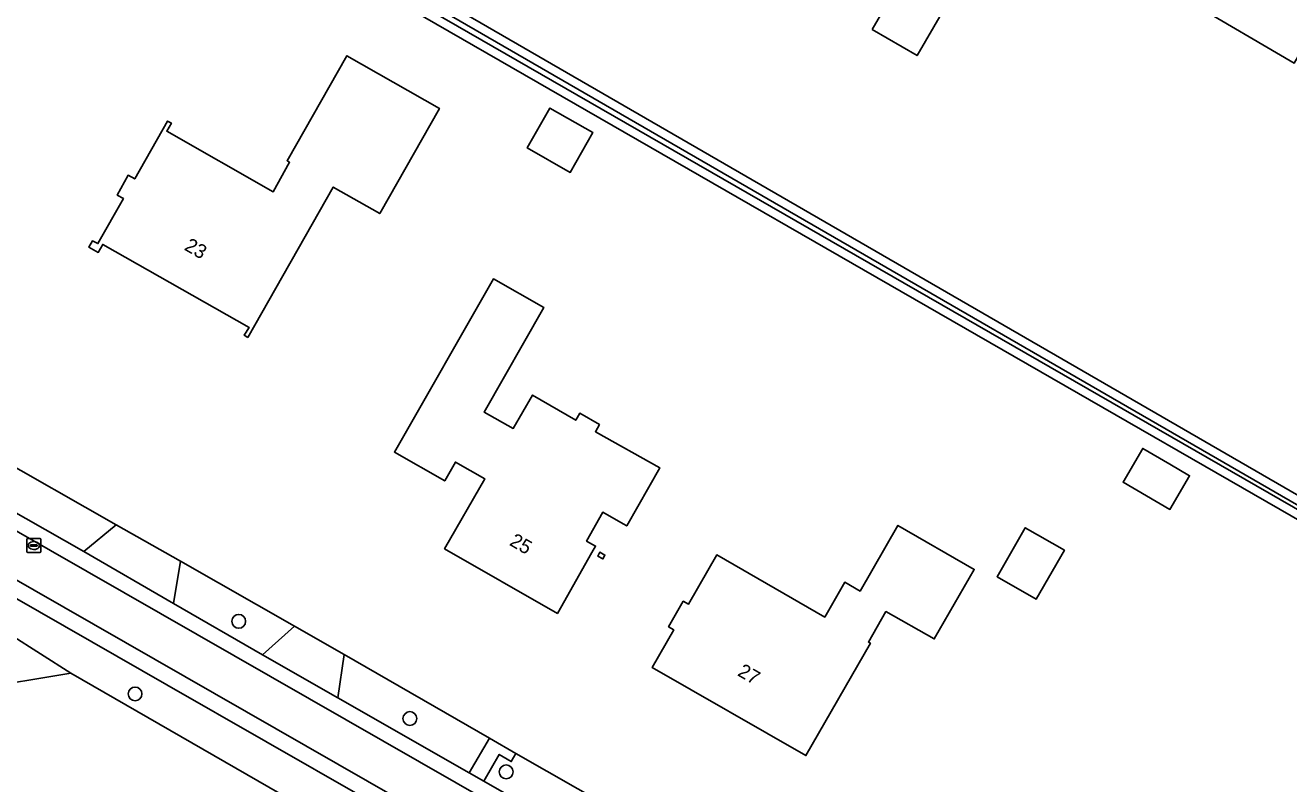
# Model space of a CAD drawing. Extents: x 156502 to 159075, y 384229 to 386100.
# Drawn here: x 157051.2 to 157141.1, y 385765 to 385818.9 of the extents above; entities that cross this region are included whole.
import ezdxf

# ---------------------------------------------------------------- set-up
doc = ezdxf.new("R2010")
doc.units = 0
for name, color, linetype in [('IMGEO_Berm_groen', 7, 'Continuous'), ('IMGEO_Boom', 7, 'Continuous'), ('IMGEO_Erf', 7, 'Continuous'), ('IMGEO_Groenvoorziening', 7, 'Continuous'), ('IMGEO_Hek', 7, 'Continuous'), ('IMGEO_Muur', 7, 'Continuous'), ('IMGEO_Oever', 7, 'Continuous'), ('IMGEO_Pand', 7, 'Continuous'), ('IMGEO_Pand_nummerreeks', 7, 'Continuous'), ('IMGEO_Rijbaan_lokaal_gesloten', 7, 'Continuous'), ('IMGEO_Rijbaan_lokaal_halfverhard', 7, 'Continuous'), ('IMGEO_Rijbaan_lokaal_open', 7, 'Continuous'), ('IMGEO_Rioolput', 7, 'Continuous'), ('IMGEO_Voetpad_open', 7, 'Continuous'), ('IMGEO_Waterloop', 7, 'Continuous')]:
    doc.layers.add(name, color=color, linetype=linetype)

msp = doc.modelspace()

# ---------------------------------------------------------------- linework, layer by layer
at = {"layer": 'IMGEO_Berm_groen'}
for points in [[(157062.278, 385780.824), (157061.801, 385777.83), (157068.127, 385774.18), (157070.393, 385776.216)], [(157073.942, 385774.201), (157073.474, 385771.108), (157082.83, 385765.787), (157084.266, 385768.252)], [(157086.152, 385767.162), (157085.817, 385766.586), (157084.961, 385767.091), (157083.861, 385765.187), (157098.368, 385756.889), (157101.744, 385758.276)]]:
    msp.add_lwpolyline(points, close=True, dxfattribs=at)
at = {"layer": 'IMGEO_Boom'}
for centre in [(157066.435, 385776.556), (157059.057, 385771.395), (157078.606, 385769.643), (157085.455, 385765.849)]:
    msp.add_circle(centre, 0.489, dxfattribs=at)
at = {"layer": 'IMGEO_Erf'}
for points in [[(157042.786, 385843.67), (157065.314, 385829.887), (157068.346, 385827.983), (157173.435, 385767.228), (157172.677, 385766.006), (157064.372, 385828.327), (157041.356, 385841.775)], [(157146.528, 385824.906), (157141.519, 385816.264), (157134.144, 385820.573)], [(157048.701, 385788.533), (157057.714, 385783.415), (157062.278, 385780.824), (157070.393, 385776.216), (157073.942, 385774.201), (157084.266, 385768.252), (157086.152, 385767.162), (157101.744, 385758.276), (157104.7, 385756.591), (157109.515, 385753.847), (157111.678, 385752.607), (157114.022, 385751.264), (157119.086, 385748.362), (157121.522, 385746.887), (157123.015, 385746.039), (157125.376, 385744.699), (157127.595, 385743.439), (157130.921, 385741.579), (157131.197, 385741.421), (157144.11, 385733.995)], [(157147.432, 385715.812), (157133.773, 385723.654), (157134.821, 385725.475), (157132.597, 385726.756), (157131.792, 385725.315), (157113.077, 385736.144), (157108.687, 385738.705), (157108.063, 385741.81), (157080.131, 385758.103), (157080.304, 385758.402), (157074.239, 385761.861), (157074.046, 385761.597), (157054.491, 385772.88), (157047.62, 385771.736)]]:
    msp.add_lwpolyline(points, dxfattribs=at)
for points in [[(157111.485, 385818.64), (157113.86, 385822.753), (157117.067, 385820.902), (157114.692, 385816.789)], [(157067.08, 385796.742), (157066.82, 385796.909), (157067.171, 385797.456), (157056.763, 385803.368), (157056.438, 385802.793), (157055.779, 385803.165), (157056.02, 385803.617), (157056.419, 385803.418), (157058.233, 385806.623), (157057.796, 385806.877), (157058.566, 385808.281), (157059.03, 385808.027), (157061.37, 385812.141), (157061.645, 385811.981), (157061.316, 385811.411), (157068.883, 385807.115), (157070.049, 385809.211), (157069.866, 385809.315), (157074.122, 385816.781), (157080.705, 385813.039), (157076.458, 385805.561), (157073.154, 385807.438)], [(157090.018, 385808.489), (157086.958, 385810.227), (157088.567, 385813.06), (157091.627, 385811.322)], [(157094.034, 385783.344), (157093.774, 385783.484), (157092.329, 385784.314), (157091.181, 385782.261), (157091.819, 385781.904), (157091.56, 385781.44), (157089.098, 385777.114), (157081.073, 385781.715), (157083.929, 385786.699), (157081.847, 385787.885), (157081.084, 385786.547), (157077.502, 385788.588), (157084.548, 385800.906), (157088.147, 385798.874), (157083.885, 385791.439), (157085.956, 385790.275), (157087.339, 385792.644), (157090.403, 385790.86), (157090.692, 385791.357), (157092.087, 385790.545), (157091.801, 385790.041), (157096.381, 385787.475)], [(157132.674, 385787.725), (157134.071, 385786.91), (157132.672, 385784.511), (157129.345, 385786.451), (157130.745, 385788.851)], [(157113.324, 385783.376), (157118.757, 385780.244), (157115.909, 385775.303), (157112.473, 385777.255), (157111.225, 385775.078), (157111.364, 385774.999), (157106.783, 385767.009), (157095.843, 385773.267), (157097.372, 385775.944), (157097.005, 385776.166), (157098.051, 385777.989), (157098.424, 385777.775), (157100.433, 385781.277), (157108.121, 385776.862), (157109.544, 385779.339), (157110.637, 385778.713)], [(157122.386, 385783.214), (157125.162, 385781.614), (157123.152, 385778.127), (157120.376, 385779.727)], [(157092.485, 385781.264), (157092.341, 385780.999), (157091.968, 385781.202), (157092.112, 385781.467)]]:
    msp.add_lwpolyline(points, close=True, dxfattribs=at)
at = {"layer": 'IMGEO_Groenvoorziening'}
for points in [[(157048.701, 385788.533), (157048.579, 385793.832), (157048.565, 385801.621), (157048.314, 385802.061), (157045.399, 385797.293), (157048.506, 385785.444), (157055.407, 385781.512), (157057.714, 385783.415)], [(157048.686, 385779.263), (157047.987, 385776.991), (157054.491, 385772.88), (157074.046, 385761.597), (157074.239, 385761.861), (157075.399, 385763.984), (157061.322, 385772.036)], [(157047.987, 385776.991), (157047.892, 385775.032), (157046.412, 385772.497), (157046.044, 385771.329), (157045.742, 385769.133), (157042.959, 385732.042), (157041.74, 385723.537), (157053.67, 385716.85), (157053.851, 385718.152), (157042.415, 385724.776), (157044.054, 385732.143), (157045.294, 385741.29), (157045.604, 385750.127), (157045.953, 385758.926), (157047.62, 385771.736), (157054.491, 385772.88)]]:
    msp.add_lwpolyline(points, close=True, dxfattribs=at)
at = {"layer": 'IMGEO_Hek'}
for points in [[(157048.314, 385802.061), (157048.565, 385801.621), (157048.579, 385793.832), (157048.701, 385788.533), (157057.714, 385783.415)], [(157057.714, 385783.415), (157062.278, 385780.824)], [(157062.278, 385780.824), (157070.393, 385776.216)], [(157070.393, 385776.216), (157073.942, 385774.201)], [(157073.942, 385774.201), (157084.266, 385768.252)], [(157074.046, 385761.597), (157054.491, 385772.88)], [(157084.266, 385768.252), (157086.152, 385767.162)], [(157086.152, 385767.162), (157101.744, 385758.276)]]:
    msp.add_lwpolyline(points, dxfattribs=at)
at = {"layer": 'IMGEO_Muur'}
for points in [[(157091.968, 385781.202), (157092.112, 385781.467), (157092.485, 385781.264)], [(157092.341, 385780.999), (157091.968, 385781.202)], [(157092.485, 385781.264), (157092.341, 385780.999)]]:
    msp.add_lwpolyline(points, dxfattribs=at)
at = {"layer": 'IMGEO_Oever'}
for points in [[(157036.041, 385834.964), (157036.588, 385835.458), (157041.356, 385841.775), (157064.372, 385828.327), (157172.677, 385766.006), (157173.435, 385767.228), (157068.346, 385827.983), (157065.314, 385829.887), (157042.786, 385843.67), (157047.224, 385849.55), (157062.244, 385869.451), (157069.688, 385879.771), (157078.432, 385891.893), (157077.479, 385892.687), (157076.448, 385893.546)], [(157042.409, 385843.171), (157064.986, 385829.358), (157068.025, 385827.45), (157172.568, 385767.011), (157172.466, 385766.846), (157064.684, 385828.865), (157041.733, 385842.275)]]:
    msp.add_lwpolyline(points, dxfattribs=at)
at = {"layer": 'IMGEO_Pand'}
for points in [[(157134.715, 385841.68), (157130.951, 385835.263), (157140.002, 385829.967), (157139.464, 385829.042), (157139.17, 385829.213), (157134.144, 385820.573), (157141.519, 385816.264), (157146.528, 385824.906), (157141.44, 385827.871), (157141.989, 385828.812), (157142.29, 385828.637), (157146.045, 385835.121)], [(157111.485, 385818.64), (157114.692, 385816.789), (157117.067, 385820.902), (157113.86, 385822.753)], [(157067.08, 385796.742), (157073.154, 385807.438), (157076.458, 385805.561), (157080.705, 385813.039), (157074.122, 385816.781), (157069.866, 385809.315), (157070.049, 385809.211), (157068.883, 385807.115), (157061.316, 385811.411), (157061.645, 385811.981), (157061.37, 385812.141), (157059.03, 385808.027), (157058.566, 385808.281), (157057.796, 385806.877), (157058.233, 385806.623), (157056.419, 385803.418), (157056.02, 385803.617), (157055.779, 385803.165), (157056.438, 385802.793), (157056.763, 385803.368), (157067.171, 385797.456), (157066.82, 385796.909)], [(157086.958, 385810.227), (157090.018, 385808.489), (157091.627, 385811.322), (157088.567, 385813.06)], [(157093.774, 385783.484), (157094.034, 385783.344), (157096.381, 385787.475), (157091.801, 385790.041), (157092.087, 385790.545), (157090.692, 385791.357), (157090.403, 385790.86), (157087.339, 385792.644), (157085.956, 385790.275), (157083.885, 385791.439), (157088.147, 385798.874), (157084.548, 385800.906), (157077.502, 385788.588), (157081.084, 385786.547), (157081.847, 385787.885), (157083.929, 385786.699), (157081.073, 385781.715), (157089.098, 385777.114), (157091.56, 385781.44), (157091.819, 385781.904), (157091.181, 385782.261), (157092.329, 385784.314)], [(157129.345, 385786.451), (157132.672, 385784.511), (157134.071, 385786.91), (157132.674, 385787.725), (157130.745, 385788.851)], [(157106.783, 385767.009), (157111.364, 385774.999), (157111.225, 385775.078), (157112.473, 385777.255), (157115.909, 385775.303), (157118.757, 385780.244), (157113.324, 385783.376), (157110.637, 385778.713), (157109.544, 385779.339), (157108.121, 385776.862), (157100.433, 385781.277), (157098.424, 385777.775), (157098.051, 385777.989), (157097.005, 385776.166), (157097.372, 385775.944), (157095.843, 385773.267)], [(157120.376, 385779.727), (157123.152, 385778.127), (157125.162, 385781.614), (157122.386, 385783.214)], [(157092.112, 385781.467), (157091.968, 385781.202), (157092.341, 385780.999), (157092.485, 385781.264)]]:
    msp.add_lwpolyline(points, close=True, dxfattribs=at)
at = {"layer": 'IMGEO_Rijbaan_lokaal_gesloten'}
for points in [[(157155.604, 385722.866), (157042.417, 385787.656)], [(157047.474, 385781.289), (157153.385, 385720.619)]]:
    msp.add_lwpolyline(points, dxfattribs=at)
at = {"layer": 'IMGEO_Rijbaan_lokaal_halfverhard'}
for points in [[(157042.417, 385787.656), (157155.604, 385722.866)], [(157156.009, 385723.887), (157148.433, 385728.196), (157142.675, 385731.515), (157129.529, 385739.04), (157126.176, 385740.973), (157123.969, 385742.234), (157121.61, 385743.581), (157120.125, 385744.429), (157117.587, 385745.884), (157112.582, 385748.755), (157110.239, 385750.099), (157105.201, 385752.99), (157098.368, 385756.889), (157083.861, 385765.187), (157082.83, 385765.787), (157073.474, 385771.108), (157068.127, 385774.18), (157061.801, 385777.83), (157055.407, 385781.512), (157048.506, 385785.444), (157044.158, 385787.921)], [(157047.474, 385781.289), (157047.846, 385779.743), (157048.686, 385779.263), (157061.322, 385772.036), (157075.399, 385763.984), (157081.499, 385760.496), (157110.277, 385744.036), (157115.815, 385740.863), (157122.692, 385736.917), (157122.862, 385737.211), (157131.139, 385732.504), (157143.135, 385725.639), (157151.556, 385720.809)], [(157153.385, 385720.619), (157047.474, 385781.289)]]:
    msp.add_lwpolyline(points, dxfattribs=at)
at = {"layer": 'IMGEO_Rijbaan_lokaal_open'}
for points in [[(157055.407, 385781.512), (157061.801, 385777.83), (157062.278, 385780.824), (157057.714, 385783.415)], [(157068.127, 385774.18), (157073.474, 385771.108), (157073.942, 385774.201), (157070.393, 385776.216)]]:
    msp.add_lwpolyline(points, close=True, dxfattribs=at)
at = {"layer": 'IMGEO_Rioolput'}
for p, q in [((157051.354, 385781.521), (157051.354, 385782.373)), ((157051.429, 385782.447), (157052.281, 385782.447)), ((157051.613, 385781.941), (157051.613, 385781.953)), ((157052.051, 385781.904), (157051.653, 385781.904)), ((157051.656, 385781.99), (157052.054, 385781.99)), ((157051.842, 385782.227), (157051.867, 385782.227)), ((157052.097, 385781.953), (157052.097, 385781.941)), ((157052.355, 385782.373), (157052.355, 385781.521)), ((157052.281, 385781.447), (157051.429, 385781.447)), ((157051.865, 385781.667), (157051.84, 385781.667))]:
    msp.add_line(p, q, dxfattribs=at)
for points in [[(157051.354, 385781.521), (157051.354, 385782.373)], [(157051.429, 385782.447), (157052.281, 385782.447)], [(157052.355, 385782.373), (157052.355, 385781.521)], [(157052.281, 385781.447), (157051.429, 385781.447)]]:
    msp.add_lwpolyline(points, dxfattribs=at)
for centre, radius, start, end in [((157051.431, 385782.371), 0.0765, 91.55205, 178.44795), ((157051.431, 385782.371), 0.0765, 91.55205, 178.44795), ((157051.653, 385781.95), 0.0403, 85.87752, 175.75265), ((157051.65, 385781.94), 0.0366, 178.93798, 274.71019), ((157052.054, 385781.947), 0.043, 264.86636, 352.45326), ((157052.058, 385781.952), 0.0386, 1.73085, 96.63898), ((157052.279, 385782.371), 0.0765, 1.55205, 88.44795), ((157052.279, 385782.371), 0.0765, 1.55205, 88.44795), ((157051.431, 385781.523), 0.0765, 181.55205, 268.44795), ((157051.431, 385781.523), 0.0765, 181.55205, 268.44795), ((157052.279, 385781.523), 0.0765, 271.55205, 358.44795), ((157052.279, 385781.523), 0.0765, 271.55205, 358.44795)]:
    msp.add_arc(centre, radius, start, end, dxfattribs=at)
for centre, major_axis, ratio, start_param, end_param in [((157051.841, 385781.947), (-0.387, 0.002), 0.722429, 4.712389, 7.853982), ((157051.866, 385781.947), (-0.39, 0.002), 0.717154, 1.570796, 4.712389)]:
    msp.add_ellipse(centre, major_axis=major_axis, ratio=ratio, start_param=start_param, end_param=end_param, dxfattribs=at)
at = {"layer": 'IMGEO_Voetpad_open'}
msp.add_lwpolyline([(157082.83, 385765.787), (157083.861, 385765.187), (157084.961, 385767.091), (157085.817, 385766.586), (157086.152, 385767.162), (157084.266, 385768.252)], close=True, dxfattribs=at)
at = {"layer": 'IMGEO_Waterloop'}
msp.add_lwpolyline([(157041.733, 385842.275), (157064.684, 385828.865), (157172.466, 385766.846), (157172.568, 385767.011), (157068.025, 385827.45), (157064.986, 385829.358), (157042.409, 385843.171)], dxfattribs=at)

# ---------------------------------------------------------------- texts
at = {"layer": 'IMGEO_Pand_nummerreeks'}
for s, rotation, p in [('23', 330.40197, (157062.496, 385803.01)), ('25', 330.17808, (157085.624, 385782.01)), ('27', 330.22817, (157101.849, 385772.734))]:
    msp.add_text(s, height=1, rotation=rotation, dxfattribs=at).set_placement(p)

doc.saveas('drawing.dxf')
